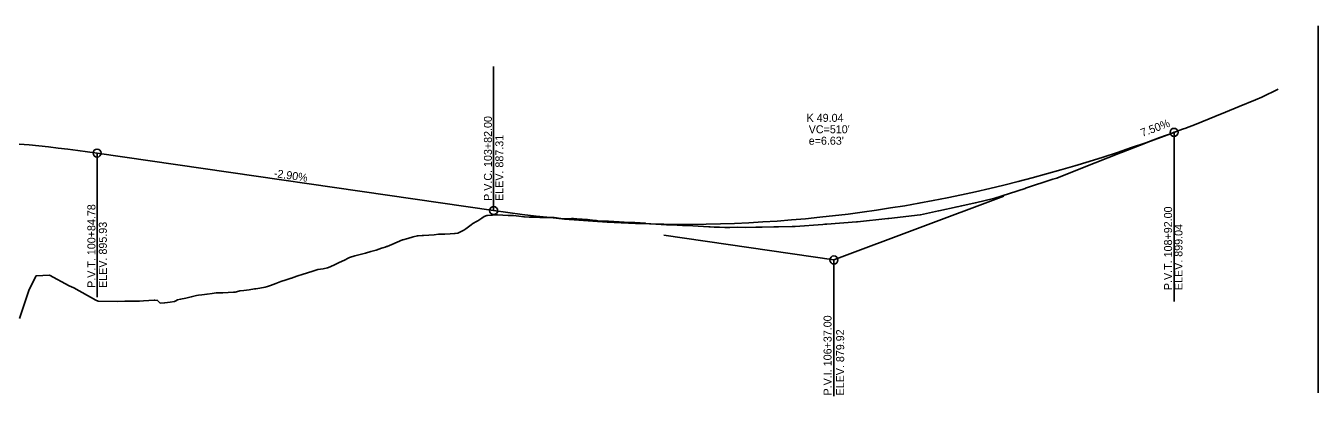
# Model space of a CAD drawing. Extents: x 1098669 to 1198896, y 698679 to 704410.
# Drawn here: x 1111699 to 1112668, y 699198 to 699475 of the extents above; entities that cross this region are included whole.
import ezdxf

# ---------------------------------------------------------------- set-up
doc = ezdxf.new("R2010")
doc.units = 0
for name, color, linetype in [('R_Axis', 7, 'Continuous'), ('R_No Plot', 7, 'Continuous'), ('R_Vert Alg', 7, 'Continuous'), ('R_Vert Alg Annot', 7, 'Continuous')]:
    doc.layers.add(name, color=color, linetype=linetype)

msp = doc.modelspace()

# ---------------------------------------------------------------- linework, layer by layer
at = {"layer": 'R_Axis'}
msp.add_line((1112667.57, 699200.03), (1112667.57, 699475.03), dxfattribs=at)
at = {"layer": 'R_No Plot'}
for points in [[(1112567.57, 699398.21), (1112576.02, 699401.37), (1112590.16, 699407.04), (1112598.09, 699410.35), (1112608.33, 699414.49), (1112620.59, 699419.65), (1112625.23, 699421.71), (1112637.57, 699427.51)], [(1112468.81, 699360.05), (1112471.58, 699360.95), (1112485.97, 699366.69), (1112486.03, 699366.71), (1112500.48, 699372.47), (1112500.49, 699372.48), (1112500.5, 699372.48), (1112519.38, 699379.82), (1112520.13, 699380.12), (1112538.17, 699387.15), (1112539.96, 699387.88), (1112556.98, 699394.15), (1112559.69, 699395.28), (1112560.21, 699395.49), (1112563.19, 699396.6), (1112566.7, 699397.89), (1112567.57, 699398.21)], [(1111694.1, 699255.8), (1111701.32, 699277.5), (1111706.62, 699287.66), (1111716.72, 699288.2), (1111731.31, 699280.28), (1111734.97, 699278.64), (1111751.46, 699269.5), (1111753.12, 699268.77), (1111767.76, 699268.55), (1111773.21, 699268.77), (1111783.25, 699268.72), (1111784.13, 699268.72), (1111787.21, 699268.91), (1111791.17, 699269.16), (1111795.13, 699269.42), (1111795.52, 699269.44), (1111797.71, 699269.32), (1111799.09, 699267.87), (1111799.69, 699267.23), (1111802.85, 699267.51), (1111803.04, 699267.53), (1111807, 699268.03), (1111810.32, 699268.42), (1111810.96, 699268.86), (1111811.35, 699269.13), (1111812.65, 699269.79), (1111814.92, 699270.26), (1111818.88, 699271.11), (1111822.84, 699272.01), (1111826.8, 699272.94), (1111828.35, 699273.32), (1111830.76, 699273.59), (1111834.72, 699274.06), (1111834.82, 699274.08), (1111838.68, 699274.58), (1111841.52, 699274.97), (1111842.64, 699274.99), (1111846.6, 699275.12), (1111850.56, 699275.29), (1111854.52, 699275.51), (1111855.78, 699275.59), (1111858.47, 699276.28), (1111859.27, 699276.5), (1111862.43, 699276.85), (1111866.39, 699277.36), (1111870.35, 699277.95), (1111871.3, 699278.11), (1111874.31, 699278.61), (1111878.27, 699279.35), (1111880.04, 699279.71), (1111882.23, 699280.48), (1111886.19, 699281.95), (1111890.11, 699283.48), (1111890.15, 699283.49), (1111894.11, 699284.73), (1111897.91, 699286.01), (1111898.07, 699286.06), (1111902.03, 699287.48), (1111902.75, 699287.75), (1111905.99, 699288.67), (1111909.95, 699289.89), (1111913.91, 699291.18), (1111916.91, 699292.23), (1111917.86, 699292.39), (1111921.82, 699293.12), (1111924.98, 699293.78), (1111925.78, 699294.11), (1111929.74, 699295.82), (1111933.7, 699297.64), (1111937.66, 699299.56), (1111940.58, 699301.05), (1111941.62, 699301.4), (1111945.58, 699302.83), (1111945.59, 699302.83), (1111949.54, 699303.75), (1111953.5, 699304.76), (1111957.46, 699305.88), (1111961.42, 699307.1), (1111965.38, 699308.42), (1111966.51, 699308.83), (1111968.23, 699309.32), (1111969.34, 699309.63), (1111969.86, 699309.8), (1111973.29, 699311.18), (1111977.25, 699312.89), (1111981.21, 699314.71), (1111981.46, 699314.83), (1111985.17, 699315.79), (1111989.13, 699316.85), (1111992.39, 699317.75), (1111993.09, 699317.77), (1111996.08, 699317.87), (1111997.05, 699317.94), (1112001.01, 699318.25), (1112004.97, 699318.59), (1112008.19, 699318.89), (1112008.93, 699318.91), (1112012.89, 699319.07), (1112016.85, 699319.25), (1112020.14, 699319.41), (1112020.81, 699319.47), (1112022.81, 699319.65), (1112024.77, 699320.66), (1112027.21, 699321.93), (1112028.73, 699323.01), (1112032.68, 699325.88), (1112034.05, 699326.89), (1112036.64, 699328.37), (1112037.68, 699328.97), (1112040.6, 699330.94), (1112042.52, 699332.26), (1112044.56, 699332.88), (1112044.94, 699333), (1112048.52, 699333.32), (1112049.1, 699333.37), (1112050.13, 699333.51), (1112052.48, 699333.39), (1112056.44, 699333.2), (1112060.4, 699333.02), (1112064.14, 699332.88), (1112064.36, 699332.85), (1112068.32, 699332.44), (1112072.28, 699332.04), (1112072.67, 699332), (1112076.24, 699331.82), (1112080.2, 699331.63), (1112080.46, 699331.62), (1112084.16, 699331.53), (1112088.11, 699331.44), (1112092.07, 699331.38), (1112095.02, 699331.34), (1112096.03, 699331.24), (1112096.64, 699331.18), (1112098.23, 699330.96), (1112099.99, 699330.79), (1112102.48, 699330.55), (1112103.24, 699330.39), (1112103.95, 699330.43), (1112107.91, 699330.64), (1112109.4, 699330.72), (1112111.87, 699330.56), (1112115.45, 699330.32), (1112115.83, 699330.27), (1112119.79, 699329.84), (1112123.75, 699329.41), (1112126.58, 699329.11), (1112127.71, 699329.04), (1112131.67, 699328.83), (1112135.13, 699328.64), (1112135.63, 699328.61), (1112139.59, 699328.35), (1112141.2, 699328.25), (1112143.54, 699328.14), (1112147.5, 699327.98), (1112151.46, 699327.82), (1112154.76, 699327.7), (1112154.86, 699327.69), (1112155.02, 699327.69), (1112155.42, 699327.66), (1112159.38, 699327.37), (1112163.34, 699327.09), (1112163.59, 699327.07), (1112167.3, 699326.74), (1112171.17, 699326.4), (1112171.26, 699326.39), (1112171.47, 699326.36), (1112171.56, 699326.36), (1112175.22, 699326.22), (1112179.18, 699326.07), (1112183.14, 699325.9), (1112187.1, 699325.72), (1112191.06, 699325.53), (1112192.65, 699325.45), (1112195.02, 699325.37), (1112195.2, 699325.36), (1112198.98, 699325.17), (1112202.93, 699324.96), (1112206.89, 699324.74), (1112210.85, 699324.5), (1112211.77, 699324.45), (1112214.81, 699324.31), (1112218.68, 699324.12), (1112218.77, 699324.12), (1112222.73, 699324.07), (1112226.12, 699324.02), (1112226.69, 699324.03), (1112232.36, 699324.13), (1112238.4, 699324.05), (1112246.03, 699324.21), (1112250.72, 699324.17), (1112259.67, 699324.38), (1112263.07, 699324.36), (1112273.29, 699324.63), (1112275.45, 699324.74), (1112296.33, 699326.31), (1112297.81, 699326.38), (1112299.18, 699326.45), (1112321.54, 699328.16), (1112322.19, 699328.2), (1112345.09, 699330.73), (1112345.85, 699330.79), (1112369.18, 699333.39), (1112369.5, 699333.41), (1112383.1, 699336.44), (1112383.2, 699336.46), (1112396.88, 699339.5), (1112396.9, 699339.5), (1112400.38, 699340.28), (1112410.6, 699342.54), (1112410.66, 699342.56), (1112424.3, 699345.58), (1112424.54, 699345.65), (1112447.94, 699353.26), (1112448.15, 699353.33), (1112468.81, 699360.05)]]:
    msp.add_lwpolyline(points, dxfattribs=at)
at = {"layer": 'R_Vert Alg'}
for p, q in [((1112049.57, 699336.6), (1112049.57, 699444.6)), ((1112559.57, 699268.56), (1112559.57, 699395.25)), ((1111752.35, 699379.7), (1111752.35, 699271.7)), ((1111752.35, 699379.7), (1112049.57, 699336.6)), ((1112304.57, 699299.62), (1112432.07, 699347.44)), ((1112177.07, 699318.11), (1112304.57, 699299.62)), ((1112304.57, 699299.62), (1112304.57, 699197.62))]:
    msp.add_line(p, q, dxfattribs=at)
for points in [[(1112049.57, 699336.6), (1112060.19, 699335.12), (1112070.82, 699333.75), (1112081.44, 699332.49), (1112092.07, 699331.36), (1112102.69, 699330.33), (1112113.32, 699329.43), (1112123.94, 699328.63), (1112134.57, 699327.96), (1112145.19, 699327.39), (1112155.82, 699326.95), (1112166.44, 699326.62), (1112177.07, 699326.4), (1112187.69, 699326.3), (1112198.32, 699326.31), (1112208.94, 699326.44), (1112219.57, 699326.68), (1112230.19, 699327.04), (1112240.82, 699327.51), (1112251.44, 699328.1), (1112262.07, 699328.81), (1112272.69, 699329.63), (1112283.32, 699330.56), (1112293.94, 699331.61), (1112315.19, 699334.05), (1112325.82, 699335.45), (1112336.44, 699336.96), (1112347.07, 699338.58), (1112357.69, 699340.32), (1112368.32, 699342.18), (1112378.94, 699344.15), (1112389.57, 699346.23), (1112400.19, 699348.43), (1112410.82, 699350.75), (1112421.44, 699353.18), (1112432.07, 699355.72), (1112442.69, 699358.38), (1112453.32, 699361.16), (1112463.94, 699364.05), (1112474.57, 699367.06), (1112485.19, 699370.18), (1112495.82, 699373.41), (1112506.44, 699376.77), (1112517.07, 699380.23), (1112527.69, 699383.81), (1112538.32, 699387.51), (1112548.94, 699391.32), (1112559.57, 699395.25)], [(1111694.01, 699386.42), (1111701.3, 699385.77), (1111708.6, 699385.07), (1111715.89, 699384.31), (1111723.18, 699383.49), (1111730.47, 699382.62), (1111737.76, 699381.7), (1111745.05, 699380.73), (1111752.35, 699379.7)]]:
    msp.add_lwpolyline(points, dxfattribs=at)
for centre in [(1112559.57, 699395.25), (1111752.35, 699379.7), (1112049.57, 699336.6), (1112304.57, 699299.62)]:
    msp.add_circle(centre, 3, dxfattribs=at)

# ---------------------------------------------------------------- texts
at = {"layer": 'R_Vert Alg Annot'}
for s, rotation, p in [('P.V.C. 103+82.00', 90, (1112048.28, 699343.88)), ('7.50%', 20.56758, (1112535.77, 699391.78)), ('ELEV. 887.31', 90, (1112056.85, 699343.88)), ('-2.90%', 351.74961, (1111884.52, 699361.83)), ('P.V.T. 100+84.78', 90, (1111751.06, 699278.71)), ('P.V.T. 108+92.00', 90, (1112558.07, 699277.06)), ('ELEV. 895.93', 90, (1111759.63, 699278.71)), ('ELEV. 899.04', 90, (1112565.87, 699277.06)), ('P.V.I. 106+37.00', 90, (1112302.85, 699198.13)), ('ELEV. 879.92', 90, (1112312.28, 699198.13))]:
    msp.add_text(s, height=6, rotation=rotation, dxfattribs=at).set_placement(p)
for s, p in [('K 49.04', (1112284.12, 699403.12)), ("VC=510'", (1112285.72, 699394.55)), ("e=6.63'", (1112285.72, 699385.98))]:
    msp.add_text(s, height=6, dxfattribs=at).set_placement(p)

doc.saveas('drawing.dxf')
